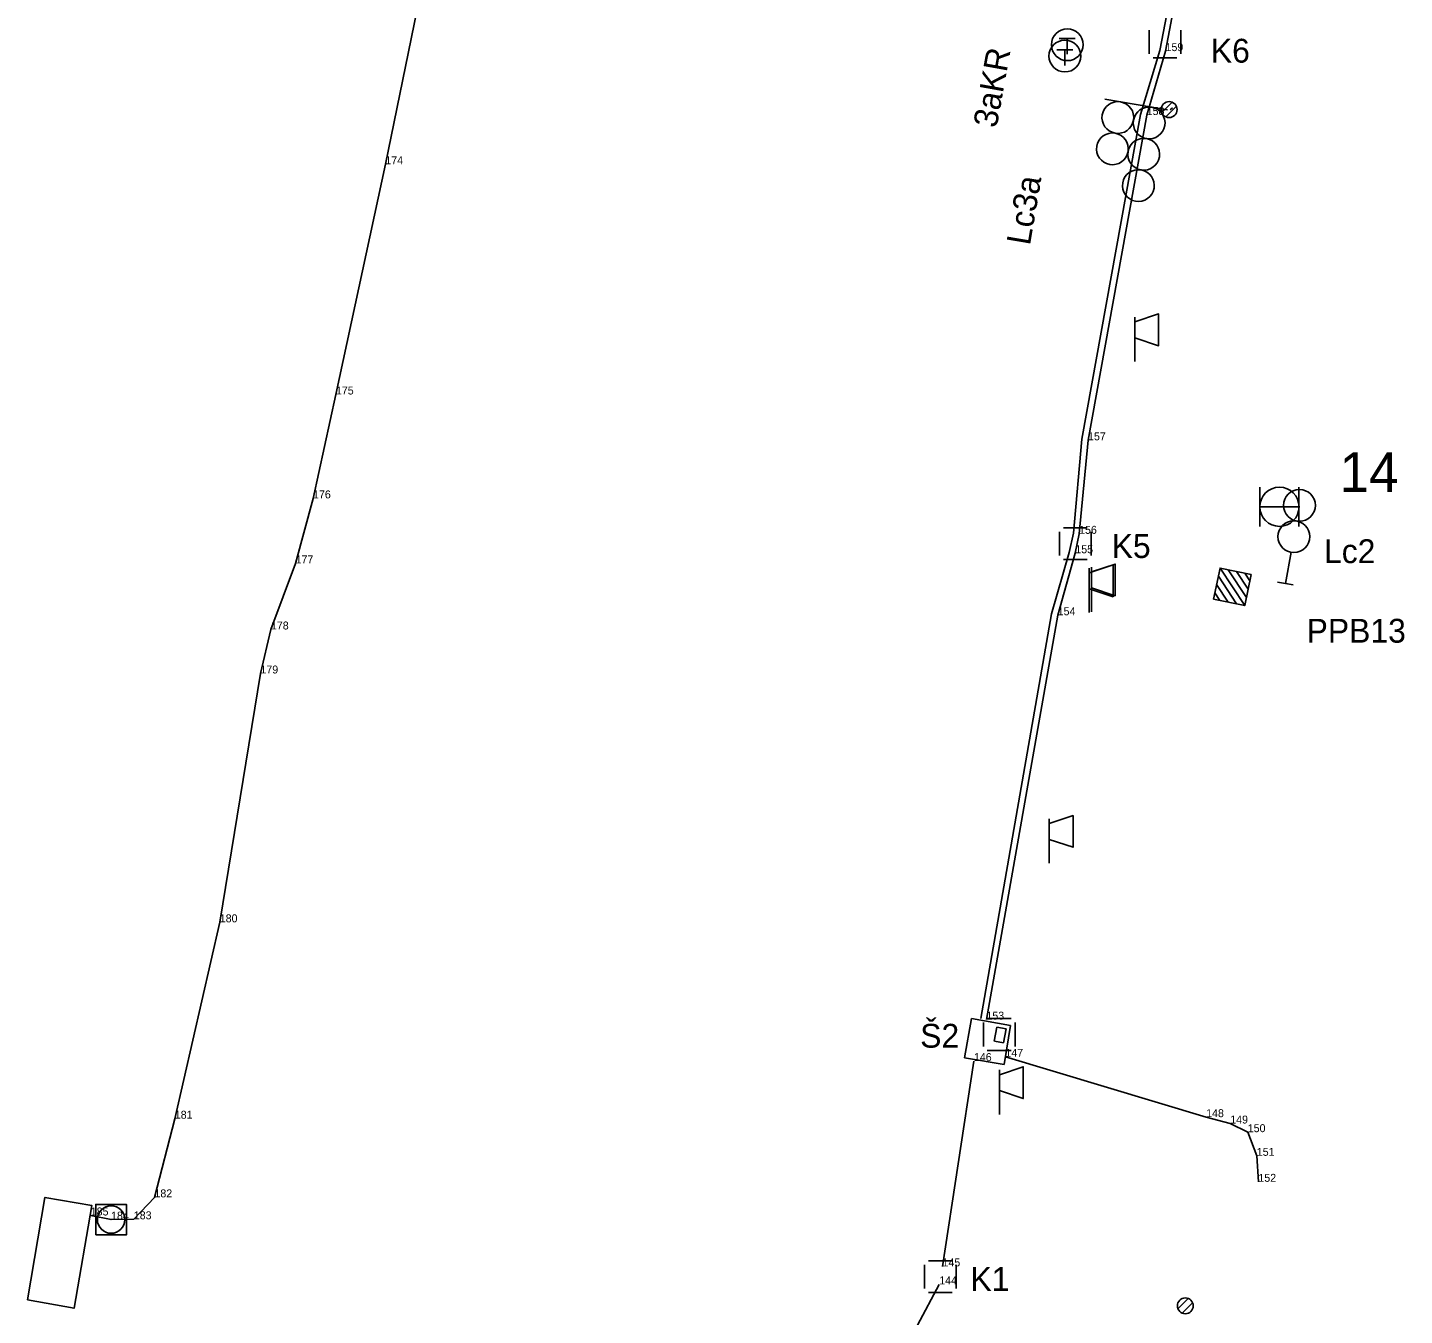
# Model space of a CAD drawing. Extents: x -866945 to -849632, y -1066564 to -1049105.
# Drawn here: x -866550.3 to -866463.7, y -1050043.8 to -1049962.8 of the extents above; entities that cross this region are included whole.
import ezdxf

# ---------------------------------------------------------------- set-up
doc = ezdxf.new("R2010")
doc.units = 0
for name, color, linetype in [('Vrstva 16', 7, 'Continuous'), ('Vrstva 2', 7, 'Continuous'), ('Vrstva 23', 7, 'Continuous'), ('Vrstva 3', 7, 'Continuous'), ('Vrstva 31', 7, 'Continuous'), ('Vrstva 32', 7, 'Continuous'), ('Vrstva 33', 7, 'Continuous'), ('Vrstva 35', 7, 'Continuous'), ('Vrstva 36', 7, 'Continuous'), ('Vrstva 52', 7, 'Continuous'), ('Vrstva 6', 7, 'Continuous')]:
    doc.layers.add(name, color=color, linetype=linetype)

msp = doc.modelspace()

# ---------------------------------------------------------------- linework, layer by layer
at = {"layer": 'Vrstva 16'}
for p, q in [((-866490.896, -1050025.147), (-866491.345, -1050027.627)), ((-866490.896, -1050025.147), (-866488.451, -1050025.586)), ((-866489.311, -1050025.684), (-866489.486, -1050026.571)), ((-866488.721, -1050025.788), (-866489.311, -1050025.684)), ((-866488.723, -1050025.8), (-866488.896, -1050026.675)), ((-866488.451, -1050025.586), (-866488.855, -1050028.039)), ((-866488.896, -1050026.675), (-866489.468, -1050026.574)), ((-866488.855, -1050028.039), (-866491.345, -1050027.627))]:
    msp.add_line(p, q, dxfattribs=at)
at = {"layer": 'Vrstva 23'}
msp.add_lwpolyline([(-866550.307, -1050042.854), (-866547.38, -1050043.38), (-866546.27, -1050036.91), (-866549.218, -1050036.404), (-866550.307, -1050042.854)], dxfattribs=at)
at = {"layer": 'Vrstva 3'}
for p, q in [((-866485.38, -1049963.46), (-866484.38, -1049963.46)), ((-866484.88, -1049963.46), (-866484.88, -1049964.46)), ((-866485.53, -1049964.17), (-866484.53, -1049964.17)), ((-866485.03, -1049964.17), (-866485.03, -1049965.17)), ((-866472.762, -1049991.708), (-866472.762, -1049994.172)), ((-866470.298, -1049991.708), (-866470.298, -1049994.172)), ((-866472.762, -1049992.94), (-866470.298, -1049992.94)), ((-866475.264, -1049996.793), (-866473.714, -1049999.159)), ((-866474.745, -1049996.901), (-866473.606, -1049998.64)), ((-866474.225, -1049997.009), (-866473.498, -1049998.12)), ((-866473.706, -1049997.118), (-866473.389, -1049997.601)), ((-866475.48, -1049997.832), (-866474.753, -1049998.943)), ((-866475.372, -1049997.312), (-866474.233, -1049999.051)), ((-866475.589, -1049998.351), (-866475.272, -1049998.834))]:
    msp.add_line(p, q, dxfattribs=at)
msp.add_lwpolyline([(-866473.306, -1049997.201), (-866473.714, -1049999.159), (-866475.672, -1049998.751), (-866475.264, -1049996.793)], close=True, dxfattribs=at)
msp.add_lwpolyline([(-866473.306, -1049997.201), (-866473.714, -1049999.159), (-866475.672, -1049998.751), (-866475.264, -1049996.793)], close=True, dxfattribs=at)
msp.add_lwpolyline([(-866473.306, -1049997.201), (-866473.714, -1049999.159), (-866475.672, -1049998.751), (-866475.264, -1049996.793), (-866473.306, -1049997.201)], dxfattribs=at)
msp.add_lwpolyline([(-866473.306, -1049997.201), (-866473.714, -1049999.159), (-866475.672, -1049998.751), (-866475.264, -1049996.793), (-866473.306, -1049997.201)], dxfattribs=at)
for centre, radius in [((-866484.88, -1049963.86), 1), ((-866485.03, -1049964.57), 1), ((-866471.525, -1049992.939), 1.232)]:
    msp.add_circle(centre, radius, dxfattribs=at)
at = {"layer": 'Vrstva 32'}
for p, q in [((-866488.771, -1050027.554), (-866476.137, -1050031.353)), ((-866476.137, -1050031.353), (-866474.623, -1050031.755)), ((-866472.951, -1050033.786), (-866473.519, -1050032.298)), ((-866472.85, -1050035.422), (-866472.951, -1050033.786))]:
    msp.add_line(p, q, dxfattribs=at)
for points in [[(-866546.33, -1050037.54), (-866545.05, -1050037.8), (-866543.62, -1050037.78), (-866542.32, -1050036.4), (-866541.04, -1050031.45), (-866538.21, -1050019.09), (-866535.65, -1050003.43), (-866534.99, -1050000.66), (-866533.44, -1049996.5), (-866532.34, -1049992.41), (-866530.9, -1049985.87), (-866527.79, -1049971.38), (-866525.62, -1049960.81), (-866523.61, -1049950.46), (-866523.14, -1049945.69), (-866523.41, -1049936.07), (-866523.16, -1049934.59)], [(-866478.26, -1049967.83), (-866478.4, -1049967.95)]]:
    msp.add_lwpolyline(points, dxfattribs=at)
msp.add_lwpolyline([(-866546.01, -1050038.76), (-866544.09, -1050038.76), (-866544.09, -1050036.84), (-866546.01, -1050036.84)], close=True, dxfattribs=at)
msp.add_circle((-866545.05, -1050037.8), 0.864, dxfattribs=at)
at = {"layer": 'Vrstva 33'}
for p, q in [((-866480.63, -1049983.8), (-866480.63, -1049981)), ((-866483.5, -1049999.6), (-866483.5, -1049996.8)), ((-866483.36, -1049999.54), (-866483.36, -1049996.74)), ((-866486.01, -1050015.37), (-866486.01, -1050012.57)), ((-866489.15, -1050031.18), (-866489.15, -1050028.38))]:
    msp.add_line(p, q, dxfattribs=at)
for points in [[(-866480.63, -1049981.3), (-866479.13, -1049980.8), (-866479.13, -1049982.8), (-866480.63, -1049982.3)], [(-866483.5, -1049997.1), (-866482, -1049996.6), (-866482, -1049998.6), (-866483.5, -1049998.1)], [(-866483.36, -1049997.04), (-866481.86, -1049996.54), (-866481.86, -1049998.54), (-866483.36, -1049998.04)], [(-866486.01, -1050012.87), (-866484.51, -1050012.37), (-866484.51, -1050014.37), (-866486.01, -1050013.87)], [(-866489.15, -1050028.68), (-866487.65, -1050028.18), (-866487.65, -1050030.18), (-866489.15, -1050029.68)]]:
    msp.add_lwpolyline(points, dxfattribs=at)
at = {"layer": 'Vrstva 35'}
for p, q in [((-866475.226, -1049944.102), (-866479.044, -1049964.211)), ((-866474.856, -1049944.148), (-866478.694, -1049964.259)), ((-866479.73, -1049964.44), (-866479.73, -1049962.94)), ((-866477.73, -1049962.94), (-866477.73, -1049964.44)), ((-866479.044, -1049964.211), (-866480.267, -1049968.242)), ((-866478.694, -1049964.259), (-866479.882, -1049968.283)), ((-866477.98, -1049964.69), (-866479.48, -1049964.69)), ((-866480.267, -1049968.242), (-866483.958, -1049988.672)), ((-866479.882, -1049968.283), (-866483.569, -1049988.752)), ((-866483.958, -1049988.672), (-866484.487, -1049994.607)), ((-866483.569, -1049988.752), (-866484.133, -1049994.64)), ((-866485.37, -1049996.01), (-866485.37, -1049994.51)), ((-866485.12, -1049994.26), (-866483.62, -1049994.26)), ((-866484.487, -1049994.607), (-866484.768, -1049995.808)), ((-866484.133, -1049994.64), (-866484.371, -1049995.861)), ((-866483.37, -1049994.51), (-866483.37, -1049996.01)), ((-866484.768, -1049995.808), (-866485.863, -1049999.67)), ((-866484.371, -1049995.861), (-866485.48, -1049999.764)), ((-866483.62, -1049996.26), (-866485.12, -1049996.26)), ((-866485.863, -1049999.67), (-866490.323, -1050025.145)), ((-866485.48, -1049999.764), (-866489.964, -1050025.214)), ((-866490.16, -1050026.9), (-866490.16, -1050025.4)), ((-866489.91, -1050025.15), (-866488.41, -1050025.15)), ((-866488.16, -1050025.4), (-866488.16, -1050026.9)), ((-866488.41, -1050027.15), (-866489.91, -1050027.15)), ((-866488.771, -1050027.554), (-866476.137, -1050031.353)), ((-866490.751, -1050027.825), (-866492.727, -1050040.745)), ((-866476.137, -1050031.353), (-866474.623, -1050031.755)), ((-866493.62, -1050040.39), (-866492.12, -1050040.39)), ((-866493.87, -1050042.14), (-866493.87, -1050040.64)), ((-866491.87, -1050040.64), (-866491.87, -1050042.14)), ((-866494.306, -1050044.446), (-866492.936, -1050041.878)), ((-866492.12, -1050042.39), (-866493.62, -1050042.39))]:
    msp.add_line(p, q, dxfattribs=at)
msp.add_lwpolyline([(-866474.623, -1050031.755), (-866473.519, -1050032.298), (-866472.951, -1050033.786), (-866472.85, -1050035.422)], dxfattribs=at)
at = {"layer": 'Vrstva 36'}
for p, q in [((-866478.931, -1049968.124), (-866478.285, -1049967.478)), ((-866478.671, -1049968.394), (-866478.016, -1049967.739)), ((-866477.911, -1050043.414), (-866477.265, -1050042.768)), ((-866477.651, -1050043.684), (-866476.996, -1050043.029))]:
    msp.add_line(p, q, dxfattribs=at)
for centre in [(-866478.47, -1049967.94), (-866477.45, -1050043.23)]:
    msp.add_circle(centre, 0.5, dxfattribs=at)
at = {"layer": 'Vrstva 6'}
for p, q in [((-866480.54, -1049967.62), (-866482.511, -1049967.28)), ((-866478.569, -1049967.96), (-866480.54, -1049967.62)), ((-866471.15, -1049997.77), (-866470.796, -1049995.802)), ((-866471.15, -1049997.77), (-866471.642, -1049997.682)), ((-866471.15, -1049997.77), (-866470.658, -1049997.858))]:
    msp.add_line(p, q, dxfattribs=at)
for centre in [(-866470.266, -1049992.849), (-866470.62, -1049994.817)]:
    msp.add_circle(centre, 1, dxfattribs=at)
for centre in [(-866481.696, -1049968.438), (-866479.725, -1049968.778), (-866482.036, -1049970.41), (-866480.065, -1049970.75), (-866480.405, -1049972.722)]:
    msp.add_ellipse(centre, major_axis=(-0.17, -0.986), ratio=0.999505, dxfattribs=at)

# ---------------------------------------------------------------- texts
at = {"layer": 'Vrstva 2'}
msp.add_text('14', height=2.5, dxfattribs=at).set_placement((-866467.748, -1049992.006))
at = {"layer": 'Vrstva 3'}
msp.add_text('3aKR', height=1.5, rotation=79.80279, dxfattribs=at).set_placement((-866489.328, -1049969.141))
msp.add_text('PPB13', height=1.5, dxfattribs=at).set_placement((-866469.816, -1050001.49))
at = {"layer": 'Vrstva 31'}
for s, p in [('K6', (-866475.842, -1049964.984)), ('K5', (-866482.086, -1049996.16)), ('Š2', (-866494.133, -1050026.98)), ('K1', (-866490.97, -1050042.292))]:
    msp.add_text(s, height=1.5, dxfattribs=at).set_placement(p)
at = {"layer": 'Vrstva 52'}
for s, p in [('159', (-866478.694, -1049964.259)), ('158', (-866479.882, -1049968.283)), ('174', (-866527.79, -1049971.38)), ('175', (-866530.9, -1049985.87)), ('157', (-866483.569, -1049988.752)), ('176', (-866532.34, -1049992.41)), ('156', (-866484.133, -1049994.64)), ('155', (-866484.371, -1049995.861)), ('177', (-866533.44, -1049996.5)), ('154', (-866485.48, -1049999.764)), ('178', (-866534.99, -1050000.66)), ('179', (-866535.65, -1050003.43)), ('180', (-866538.21, -1050019.09)), ('153', (-866489.964, -1050025.214)), ('146', (-866490.751, -1050027.825)), ('147', (-866488.771, -1050027.554)), ('181', (-866541.04, -1050031.45)), ('148', (-866476.137, -1050031.353)), ('149', (-866474.623, -1050031.755)), ('150', (-866473.519, -1050032.298)), ('151', (-866472.951, -1050033.786)), ('152', (-866472.85, -1050035.422)), ('182', (-866542.32, -1050036.4)), ('185', (-866546.33, -1050037.54)), ('184', (-866545.05, -1050037.8)), ('183', (-866543.62, -1050037.78)), ('145', (-866492.727, -1050040.745)), ('144', (-866492.936, -1050041.878))]:
    msp.add_text(s, height=0.5, dxfattribs=at).set_placement(p)
at = {"layer": 'Vrstva 6'}
msp.add_text('Lc3a', height=1.5, rotation=80.36413, dxfattribs=at).set_placement((-866487.229, -1049976.529))
msp.add_text('Lc2', height=1.5, dxfattribs=at).set_placement((-866468.721, -1049996.483))

doc.saveas('drawing.dxf')
